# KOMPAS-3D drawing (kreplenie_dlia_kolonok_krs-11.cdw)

Views: Вид 1
Referenced files: 8831-4_Кронштейн на столб.cdw
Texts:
  исп. 8831-4
  Кронштейн КРС-11
  Стяжная лента 20мм
  Уголок 50х50
  страховочный
  Скоба
  Страховочный трос
  В комплект поставки
  НЕ ВХОДИТ
  Болт М12
  Гайка М12
  Швеллер 6.5
  R.25-94TZ
  Болт М8
  Гайка М8
  Опора НФГ-5,0-02-ц
  Кронштейн для подвесной аккустической системы Community R.25-94TZ
  POLYLINE_STYLE_0.18_RGB_0_0_0
  Кронштейн
  КРС-11
Dimensions and other numbers on the sheet: 225; 50; 4; 30; 40; 140; 70; 300; 117,5; 15; 200; 1:5; 1; 8831-2-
